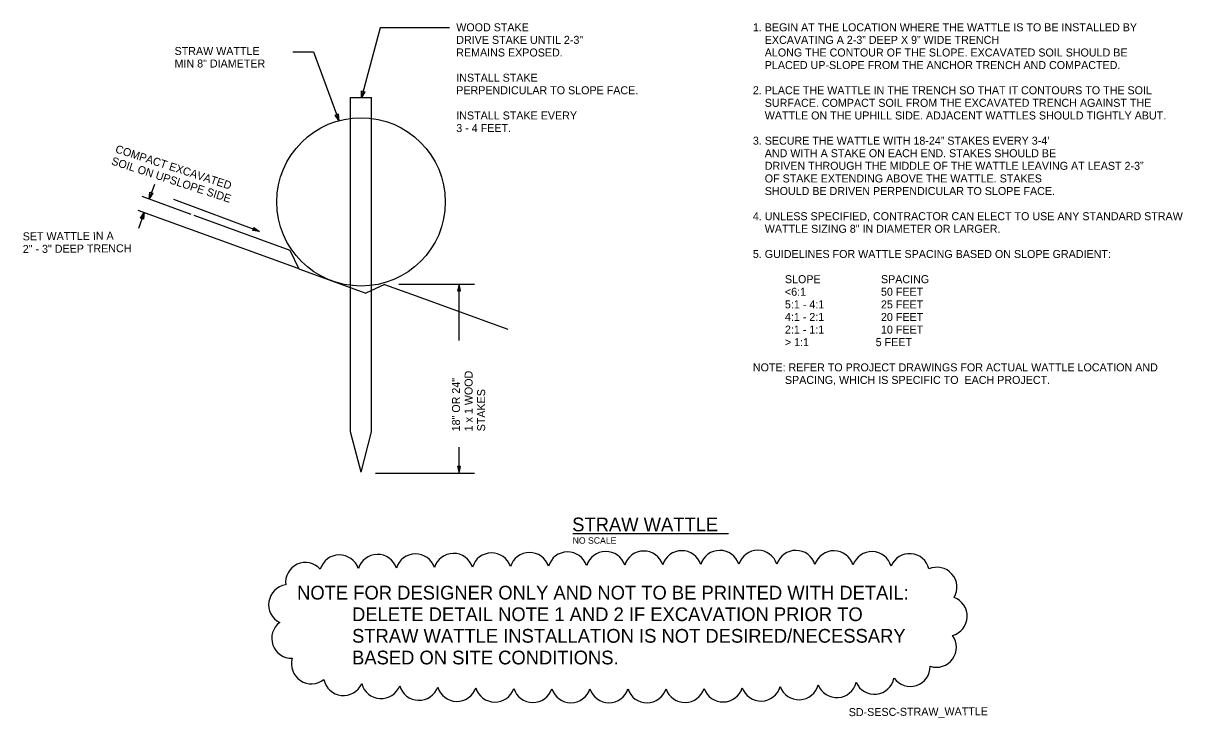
# Model space of a CAD drawing. Extents: x 9657 to 9809, y 9967 to 10057.
import ezdxf

# ---------------------------------------------------------------- set-up
doc = ezdxf.new("R2010")
doc.units = 0
for name, color, linetype in [('Default', 7, 'Continuous'), ('G-ANNO-CELL', 7, 'Continuous'), ('G-ANNO-TEXT', 7, 'Continuous')]:
    doc.layers.add(name, color=color, linetype=linetype)

# ---------------------------------------------------------------- blocks, each defined once
blk = doc.blocks.new('TERARR')
at = {"layer": 'Default'}
blk.add_lwpolyline([(-0.67, 0.17), (0, 0), (-0.67, -0.17)], close=True, dxfattribs=at)

msp = doc.modelspace()

# ---------------------------------------------------------------- linework, layer by layer
at = {"layer": 'Default'}
for p, q in [((9699.95, 10003.87), (9699.95, 10047.48)), ((9699.95, 10047.48), (9702.7, 10047.48)), ((9702.7, 10003.87), (9702.7, 10047.48)), ((9679.5, 10032.16), (9692.04, 10027.59)), ((9692.04, 10027.59), (9693.19, 10025.14)), ((9693.19, 10025.14), (9701.94, 10021.95)), ((9704.4, 10023.09), (9701.94, 10021.95)), ((9704.4, 10023.09), (9707.9, 10021.82)), ((9707.9, 10021.82), (9720.47, 10017.25)), ((9701.32, 9998.59), (9699.95, 10003.87)), ((9701.32, 9998.59), (9702.7, 10003.87))]:
    msp.add_line(p, q, dxfattribs=at)
msp.add_circle((9701.32, 10033.87), 10.99, dxfattribs=at)
at = {"layer": 'G-ANNO-CELL'}
msp.add_line((9728.94, 9990.6), (9749.24, 9990.6), dxfattribs=at)
for centre, start, end in [((9698.49, 9985.19), 18.2327, 163.2327), ((9703.46, 9985.26), 18.2327, 163.2327), ((9708.42, 9985.32), 18.2327, 163.2327), ((9713.38, 9985.39), 18.2327, 163.2327), ((9718.35, 9985.45), 18.2327, 163.2327), ((9723.31, 9985.51), 18.2327, 163.2327), ((9728.27, 9985.58), 18.2327, 163.2327), ((9733.24, 9985.64), 18.2233, 163.2233), ((9738.2, 9985.7), 18.1198, 163.1198), ((9743.16, 9985.74), 17.97, 162.97), ((9748.12, 9985.78), 17.7825, 162.7825), ((9753.08, 9985.79), 17.5385, 162.5385), ((9758.04, 9985.78), 17.2021, 162.2021), ((9763, 9985.73), 16.6943, 161.6943), ((9767.95, 9985.62), 15.7877, 160.7877), ((9772.87, 9985.36), 13.1875, 158.1875), ((9694.07, 9984.2), 42.162, 187.162), ((9776.45, 9983.58), 328.8569, 113.8569), ((9691.87, 9981.3), 98.4451, 243.4451), ((9777.79, 9979.79), 284.9718, 69.9718), ((9692.27, 9976.89), 126.8137, 271.8137), ((9776.38, 9975.72), 251.7214, 36.7214), ((9694.85, 9973.56), 163.6675, 308.6675), ((9772.96, 9973.23), 215.4735, 0.4735), ((9699.03, 9972.03), 191.1796, 336.1796), ((9763.38, 9971.77), 201.3809, 346.3809), ((9768.28, 9972.21), 204.0144, 349.0144), ((9703.93, 9971.63), 194.3868, 339.3868), ((9708.87, 9971.41), 195.5655, 340.5655), ((9713.82, 9971.27), 196.2339, 341.2339), ((9718.78, 9971.18), 196.6794, 341.6794), ((9723.74, 9971.12), 197.0036, 342.0036), ((9728.7, 9971.09), 197.2533, 342.2533), ((9733.66, 9971.08), 197.4567, 342.4567), ((9738.62, 9971.08), 197.7282, 342.7282), ((9743.58, 9971.12), 198.0928, 343.0928), ((9748.54, 9971.19), 198.5541, 343.5541), ((9753.49, 9971.31), 199.1644, 344.1644), ((9758.44, 9971.49), 200.0263, 345.0263)]:
    msp.add_arc(centre, 2.6, start, end, dxfattribs=at)
at = {"layer": 'G-ANNO-TEXT'}
for p, q in [((9674.36, 10036.13), (9673.69, 10034.27)), ((9672.74, 10034.62), (9679.13, 10032.29)), ((9688.07, 10030.02), (9676.9, 10034.2)), ((9672.2, 10032.8), (9693.08, 10025.2)), ((9673.04, 10032.49), (9672.28, 10030.41)), ((9706.23, 10023.13), (9716.13, 10023.13)), ((9714.1, 10015.76), (9714.1, 10023.13)), ((9714.1, 9998.47), (9714.1, 10001.87)), ((9703.22, 9998.47), (9716.13, 9998.47))]:
    msp.add_line(p, q, dxfattribs=at)
for points in [[(9712.87, 10056.58), (9703.8, 10056.58), (9701.37, 10047.48)], [(9692.44, 10053.45), (9695.14, 10053.45), (9698.43, 10044.48)]]:
    msp.add_lwpolyline(points, dxfattribs=at)

# ---------------------------------------------------------------- block references
for p, xscale, yscale, rotation in [((9701.37, 10047.48), 1.2655434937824, 1.2655434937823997, -104.95705746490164), ((9701.37, 10047.48), 1.2655434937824, 1.2655434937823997, -104.95705746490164), ((9698.43, 10044.48), 1.2655434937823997, 1.2655434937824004, -69.83283086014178), ((9673.69, 10034.27), 1.2655434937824, 1.2655434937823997, -110.00000000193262), ((9673.69, 10034.27), 1.2655434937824, 1.2655434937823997, -110.00000000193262), ((9673.04, 10032.49), 1.2655434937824, 1.2655434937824, 69.9999999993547), ((9673.04, 10032.49), 1.2655434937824, 1.2655434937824, 69.9999999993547), ((9688.07, 10030.02), 1.2655434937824, 1.2655434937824, -20.530473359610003), ((9714.1, 10023.13), 1.2655434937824, -1.2655434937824, 90), ((9714.1, 9998.47), 1.2655434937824, -1.2655434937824, -90)]:
    msp.add_blockref('TERARR', p, dxfattribs=dict(at, xscale=xscale, yscale=yscale, rotation=rotation))

# ---------------------------------------------------------------- texts
at = {"layer": 'G-ANNO-CELL'}
for s, height, p in [('STRAW WATTLE', 1.7929, (9728.86, 9990.87)), ('NO SCALE', 0.844, (9728.92, 9989.25)), ('NOTE FOR DESIGNER ONLY AND NOT TO BE PRINTED WITH DETAIL:', 1.7929, (9692.98, 9981.97)), ('DELETE DETAIL NOTE 1 AND 2 IF EXCAVATION PRIOR TO ', 1.7929, (9700.15, 9979.15)), ('STRAW WATTLE INSTALLATION IS NOT DESIRED/NECESSARY', 1.7929, (9700.15, 9976.33)), ('BASED ON SITE CONDITIONS. ', 1.7929, (9700.15, 9973.5))]:
    msp.add_text(s, height=height, dxfattribs=at).set_placement(p)
at = {"layer": 'G-ANNO-TEXT'}
for s, p in [('WOOD STAKE ', (9713.74, 10056.14)), ('1. BEGIN AT THE LOCATION WHERE THE WATTLE IS TO BE INSTALLED BY ', (9752.43, 10056.14)), ('DRIVE STAKE UNTIL 2-3"', (9713.74, 10054.5)), ('    EXCAVATING A 2-3” DEEP X 9” WIDE TRENCH ', (9752.43, 10054.5)), ('STRAW WATTLE', (9677, 10053.05)), ('REMAINS EXPOSED.', (9713.74, 10052.85)), ('    ALONG THE CONTOUR OF THE SLOPE. EXCAVATED SOIL SHOULD BE ', (9752.43, 10052.85)), ('MIN 8" DIAMETER', (9677, 10051.41)), ('    PLACED UP-SLOPE FROM THE ANCHOR TRENCH AND COMPACTED.', (9752.43, 10051.21)), ('INSTALL STAKE ', (9713.74, 10049.56)), ('PERPENDICULAR TO SLOPE FACE.', (9713.74, 10047.92)), ('2. PLACE THE WATTLE IN THE TRENCH SO THAT IT CONTOURS TO THE SOIL ', (9752.43, 10047.92)), ('    SURFACE. COMPACT SOIL FROM THE EXCAVATED TRENCH AGAINST THE ', (9752.43, 10046.28)), ('INSTALL STAKE EVERY ', (9713.74, 10044.63)), ('    WATTLE ON THE UPHILL SIDE. ADJACENT WATTLES SHOULD TIGHTLY ABUT. ', (9752.43, 10044.63)), ('3 - 4 FEET. ', (9713.74, 10042.99)), ('3. SECURE THE WATTLE WITH 18-24” STAKES EVERY 3-4’ ', (9752.43, 10041.34)), ('    AND WITH A STAKE ON EACH END. STAKES SHOULD BE ', (9752.43, 10039.7)), ('    DRIVEN THROUGH THE MIDDLE OF THE WATTLE LEAVING AT LEAST 2-3” ', (9752.43, 10038.06)), ('    OF STAKE EXTENDING ABOVE THE WATTLE. STAKES ', (9752.43, 10036.41)), ('    SHOULD BE DRIVEN PERPENDICULAR TO SLOPE FACE. ', (9752.43, 10034.77)), ('4. UNLESS SPECIFIED, CONTRACTOR CAN ELECT TO USE ANY STANDARD STRAW', (9752.43, 10031.48)), ('    WATTLE SIZING 8" IN DIAMETER OR LARGER.', (9752.43, 10029.84)), ('5. GUIDELINES FOR WATTLE SPACING BASED ON SLOPE GRADIENT:', (9752.43, 10026.55)), ('SLOPE', (9756.61, 10023.26)), ('SPACING', (9769.14, 10023.26)), ('<6:1', (9756.61, 10021.62)), ('50 FEET', (9769.14, 10021.62)), ('5:1 - 4:1', (9756.61, 10019.97)), ('25 FEET', (9769.14, 10019.97)), ('4:1 - 2:1', (9756.61, 10018.33)), ('20 FEET', (9769.14, 10018.33)), ('2:1 - 1:1', (9756.61, 10016.68)), ('10 FEET', (9769.14, 10016.68)), ('> 1:1', (9756.61, 10015.04)), ('         5 FEET', (9764.96, 10015.04)), ('NOTE: REFER TO PROJECT DRAWINGS FOR ACTUAL WATTLE LOCATION AND ', (9752.43, 10011.75)), ('SPACING, WHICH IS SPECIFIC TO  EACH PROJECT.', (9756.61, 10010.11))]:
    msp.add_text(s, height=1.044, dxfattribs=at).set_placement(p)
for s, rotation, p in [('COMPACT EXCAVATED', 342, (9669.18, 10040.35)), ('SOIL ON UPSLOPE SIDE', 342, (9668.67, 10038.78)), ('SET WATTLE IN A ', 0.4165, (9657.19, 10028.85)), ('2" - 3" DEEP TRENCH', 0.4165, (9657.2, 10027.2)), ('18" OR 24"', 90, (9714.23, 10003.92)), ('1 x 1 WOOD ', 90, (9715.87, 10003.92)), ('STAKES', 90, (9717.51, 10003.92)), ('SD-SESC-STRAW_WATTLE', 0.4165, (9764.94, 9966.74))]:
    msp.add_text(s, height=1.044, rotation=rotation, dxfattribs=at).set_placement(p)

doc.saveas('drawing.dxf')
